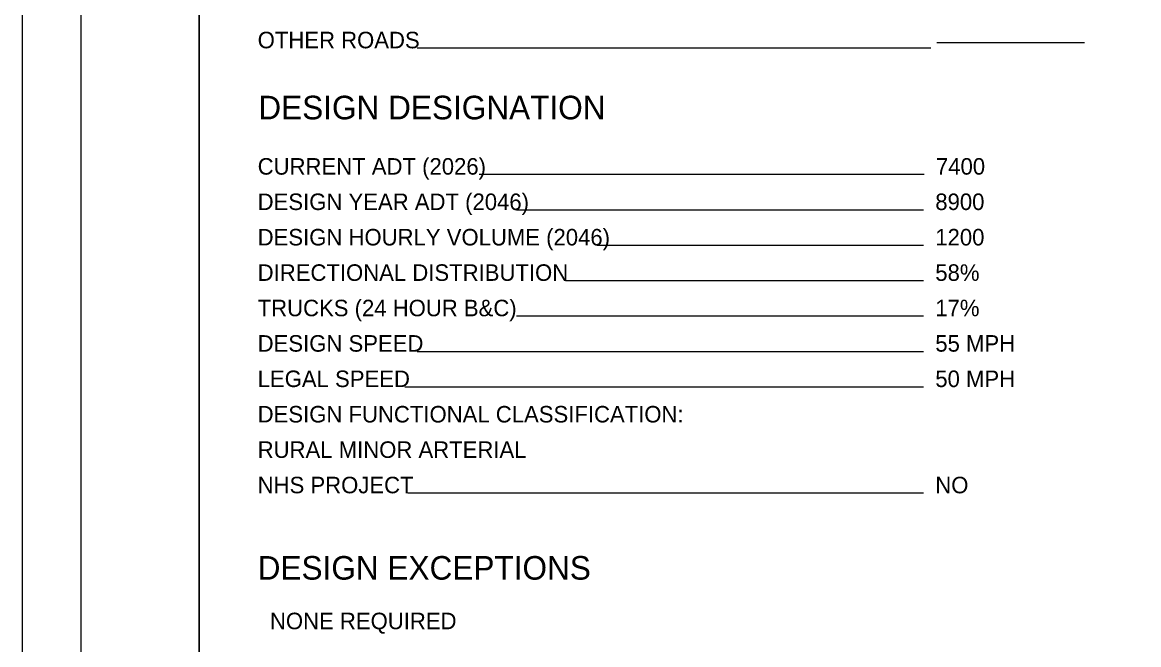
# Model space of a CAD drawing. Extents: x 0 to 42, y 0 to 22.
# Drawn here: x 0 to 9.46, y 5.82 to 11.1 of the extents above; entities that cross this region are included whole.
import ezdxf

# ---------------------------------------------------------------- set-up
doc = ezdxf.new("R2010")
doc.units = 0
for name, color, linetype in [('SH_Border', 7, 'Continuous'), ('SH_Cut_Line', 7, 'Continuous'), ('SH_Data', 7, 'Continuous'), ('SH_Text', 7, 'Continuous')]:
    doc.layers.add(name, color=color, linetype=linetype)

msp = doc.modelspace()

# ---------------------------------------------------------------- linework, layer by layer
at = {"layer": 'SH_Border'}
for points in [[(0.5, 21.5), (1.5, 21.5), (1.5, 0.5), (0.5, 0.5)], [(1.5, 21.5), (33.5, 21.5), (33.5, 0.5), (1.5, 0.5)]]:
    msp.add_lwpolyline(points, close=True, dxfattribs=at)
at = {"layer": 'SH_Cut_Line'}
msp.add_lwpolyline([(0, 0), (34, 0), (34, 22), (0, 22)], close=True, dxfattribs=at)
at = {"layer": 'SH_Data'}
for p, q in [((9, 10.9223), (7.75, 10.9223)), ((7.7, 10.8767), (3.3471, 10.8767)), ((7.6424, 9.8062), (3.871, 9.8062)), ((7.6368, 9.5062), (4.1885, 9.5062)), ((7.6368, 9.2062), (4.8723, 9.2062)), ((7.6368, 8.9062), (4.6037, 8.9062)), ((7.6368, 8.6062), (4.1885, 8.6062)), ((7.6368, 8.3062), (3.346, 8.3062)), ((7.6368, 8.0062), (3.2422, 8.0062)), ((7.6368, 7.1062), (3.2669, 7.1062))]:
    msp.add_line(p, q, dxfattribs=at)

# ---------------------------------------------------------------- texts
msp.add_text('DESIGN DESIGNATION', height=0.2, dxfattribs=at).set_placement((2, 10.2747))
at = {"layer": 'SH_Text'}
for s, height, p in [('OTHER ROADS', 0.14, (1.9944, 10.8767)), ('CURRENT ADT (2026)', 0.14, (1.9944, 9.8062)), ('7400  ', 0.14, (7.7424, 9.8062)), ('DESIGN YEAR ADT (2046)', 0.14, (1.9944, 9.5062)), ('8900  ', 0.14, (7.7368, 9.5062)), ('DESIGN HOURLY VOLUME (2046)', 0.14, (1.9944, 9.2062)), ('1200  ', 0.14, (7.7368, 9.2062)), ('DIRECTIONAL DISTRIBUTION', 0.14, (1.9944, 8.9062)), ('58%   ', 0.14, (7.7368, 8.9062)), ('TRUCKS (24 HOUR B&C)', 0.14, (1.9944, 8.6062)), ('17%   ', 0.14, (7.7368, 8.6062)), ('DESIGN SPEED', 0.14, (1.9944, 8.3062)), ('55 MPH', 0.14, (7.7368, 8.3062)), ('LEGAL SPEED', 0.14, (1.9944, 8.0062)), ('50 MPH', 0.14, (7.7368, 8.0062)), ('DESIGN FUNCTIONAL CLASSIFICATION:', 0.14, (1.9944, 7.7062)), ('RURAL MINOR ARTERIAL                            ', 0.14, (1.9944, 7.4062)), ('NHS PROJECT', 0.14, (1.9944, 7.1062)), ('NO    ', 0.14, (7.7368, 7.1062)), ('DESIGN EXCEPTIONS', 0.2, (1.9944, 6.3744)), ('  NONE REQUIRED                          ', 0.14, (1.9944, 5.9544))]:
    msp.add_text(s, height=height, dxfattribs=at).set_placement(p)

doc.saveas('drawing.dxf')
